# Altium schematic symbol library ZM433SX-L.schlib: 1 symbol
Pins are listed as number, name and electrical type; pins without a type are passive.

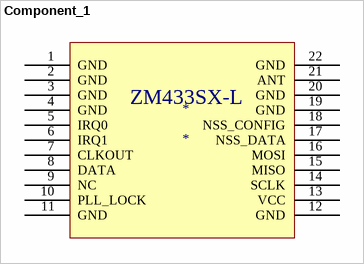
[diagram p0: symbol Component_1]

## Component_1
designator *
pins: 1 GND, 2 GND, 3 GND, 4 GND, 5 IRQ0, 6 IRQ1, 7 CLKOUT, 8 DATA, 9 NC, 10 PLL_LOCK, 11 GND, 12 GND, 13 VCC, 14 SCLK, 15 MISO, 16 MOSI, 17 NSS_DATA, 18 NSS_CONFIG, 19 GND, 20 GND, 21 ANT, 22 GND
